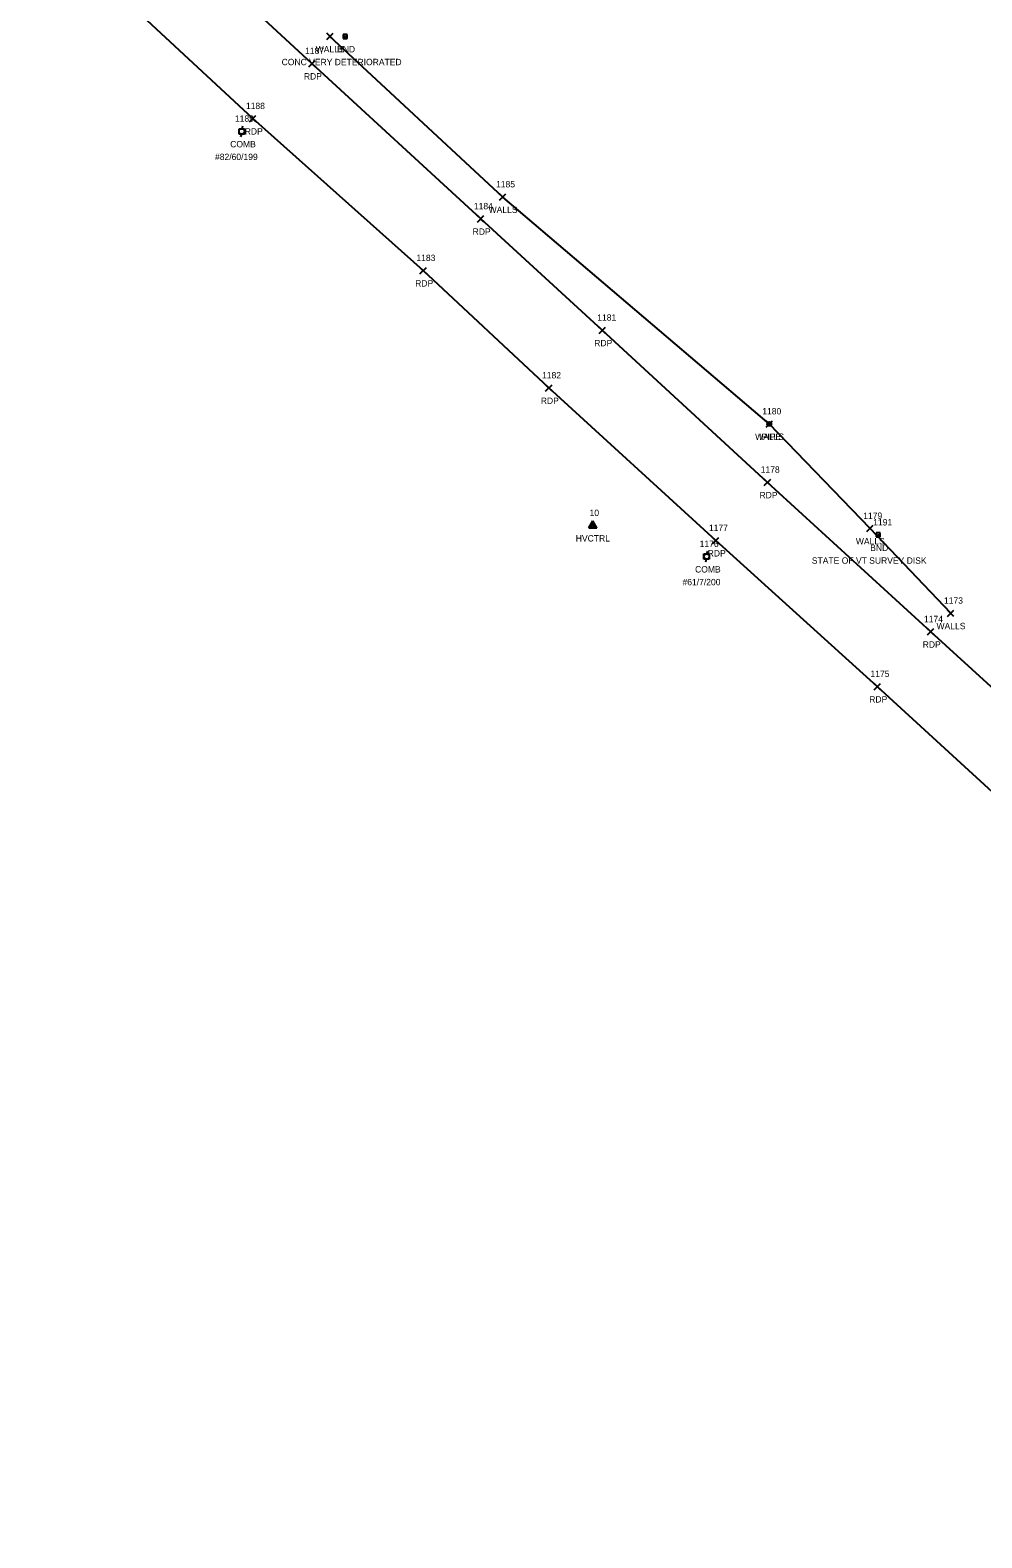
# Model space of a CAD drawing. Extents: x 1519347 to 1522636, y 378779 to 379832.
# Drawn here: x 1521076 to 1521374.1, y 378831 to 379303.7 of the extents above; entities that cross this region are included whole.
import ezdxf

# ---------------------------------------------------------------- set-up
doc = ezdxf.new("R2010")
doc.units = 0
for name, color, linetype in [('C_A', 7, 'Continuous'), ('C_I', 7, 'Continuous'), ('CPSM', 7, 'Continuous'), ('L_A', 7, 'Continuous'), ('L_I', 7, 'Continuous'), ('L_TIC', 7, 'Continuous'), ('LWS', 7, 'Continuous'), ('M_A', 7, 'Continuous'), ('M_C', 7, 'Continuous'), ('M_I', 7, 'Continuous'), ('MHBP', 7, 'Continuous'), ('MPIP', 7, 'Continuous'), ('P_A', 7, 'Continuous'), ('P_I', 7, 'Continuous'), ('P_TIC', 7, 'Continuous'), ('PET', 7, 'Continuous'), ('U_A', 7, 'Continuous'), ('U_C', 7, 'Continuous'), ('U_I', 7, 'Continuous'), ('UP', 7, 'Continuous')]:
    doc.layers.add(name, color=color, linetype=linetype)

msp = doc.modelspace()

# ---------------------------------------------------------------- linework, layer by layer
at = {"layer": 'CPSM'}
for p, q in [((1521250.98, 379147.68), (1521252.23, 379149.84)), ((1521250.98, 379147.68), (1521252.23, 379148.4)), ((1521253.48, 379147.68), (1521252.23, 379149.84)), ((1521252.23, 379148.4), (1521252.23, 379149.84)), ((1521252.23, 379148.4), (1521252.23, 379148.4)), ((1521252.23, 379148.4), (1521253.48, 379147.68)), ((1521250.98, 379147.68), (1521253.48, 379147.68))]:
    msp.add_line(p, q, dxfattribs=at)
at = {"layer": 'L_TIC'}
for points in [[(1521168.88, 379300.74), (1521170.88, 379302.74)], [(1521170.88, 379300.74), (1521168.88, 379302.74)], [(1521223.05, 379250.41), (1521225.05, 379252.41)], [(1521225.05, 379250.41), (1521223.05, 379252.41)], [(1521306.56, 379179.25), (1521308.56, 379181.25)], [(1521308.56, 379179.25), (1521306.56, 379181.25)], [(1521338.12, 379146.49), (1521340.12, 379148.49)], [(1521340.12, 379146.49), (1521338.12, 379148.49)], [(1521363.4, 379119.9), (1521365.4, 379121.9)], [(1521365.4, 379119.9), (1521363.4, 379121.9)]]:
    msp.add_lwpolyline(points, dxfattribs=at)
at = {"layer": 'LWS'}
msp.add_lwpolyline([(1521364.4, 379120.9), (1521339.12, 379147.49), (1521307.56, 379180.25), (1521224.05, 379251.41), (1521169.88, 379301.74)], dxfattribs=at)
at = {"layer": 'MHBP'}
for p, q in [((1521175.28, 379302.38), (1521174.03, 379302.38)), ((1521174.03, 379302.38), (1521174.03, 379301.13)), ((1521175.28, 379302.38), (1521174.03, 379302.38)), ((1521174.03, 379302.38), (1521174.03, 379301.13)), ((1521174.03, 379301.13), (1521175.28, 379301.13)), ((1521174.03, 379301.13), (1521175.28, 379301.13)), ((1521175.28, 379301.13), (1521175.28, 379302.38)), ((1521175.28, 379301.13), (1521175.28, 379302.38)), ((1521342.33, 379146.09), (1521341.08, 379146.09)), ((1521341.08, 379146.09), (1521341.08, 379144.84)), ((1521342.33, 379146.09), (1521341.08, 379146.09)), ((1521341.08, 379146.09), (1521341.08, 379144.84)), ((1521341.08, 379144.84), (1521342.33, 379144.84)), ((1521341.08, 379144.84), (1521342.33, 379144.84)), ((1521342.33, 379144.84), (1521342.33, 379146.09)), ((1521342.33, 379144.84), (1521342.33, 379146.09))]:
    msp.add_line(p, q, dxfattribs=at)
for centre in [(1521174.63, 379301.72), (1521341.68, 379145.42)]:
    msp.add_circle(centre, 0.0833, dxfattribs=at)
at = {"layer": 'MPIP'}
for radius in [0.625, 0.0833]:
    msp.add_circle((1521307.56, 379180.25), radius, dxfattribs=at)
at = {"layer": 'P_TIC'}
for points in [[(1521163.23, 379292.24), (1521165.23, 379294.24)], [(1521165.23, 379292.24), (1521163.23, 379294.24)], [(1521144.7, 379274.98), (1521146.7, 379276.98)], [(1521146.7, 379274.98), (1521144.7, 379276.98)], [(1521216.12, 379243.56), (1521218.12, 379245.56)], [(1521218.12, 379243.56), (1521216.12, 379245.56)], [(1521198.1, 379227.33), (1521200.1, 379229.33)], [(1521200.1, 379227.33), (1521198.1, 379229.33)], [(1521254.2, 379208.61), (1521256.2, 379210.61)], [(1521256.2, 379208.61), (1521254.2, 379210.61)], [(1521237.48, 379190.54), (1521239.48, 379192.54)], [(1521239.48, 379190.54), (1521237.48, 379192.54)], [(1521305.99, 379160.95), (1521307.99, 379162.95)], [(1521307.99, 379160.95), (1521305.99, 379162.95)], [(1521289.76, 379142.7), (1521291.76, 379144.7)], [(1521291.76, 379142.7), (1521289.76, 379144.7)], [(1521357.14, 379114.1), (1521359.14, 379116.1)], [(1521359.14, 379114.1), (1521357.14, 379116.1)], [(1521340.37, 379096.91), (1521342.37, 379098.91)], [(1521342.37, 379096.91), (1521340.37, 379098.91)]]:
    msp.add_lwpolyline(points, dxfattribs=at)
at = {"layer": 'PET'}
for points in [[(1521585.34, 378845.78), (1521563.15, 378884.68), (1521538.32, 378926.95), (1521509.26, 378967.74), (1521474.33, 379006.93), (1521436.59, 379043.66), (1521409.99, 379067.83), (1521358.14, 379115.1), (1521306.99, 379161.95), (1521255.2, 379209.61), (1521217.12, 379244.56), (1521164.23, 379293.24), (1521067.69, 379382.51), (1520997.97, 379446.49), (1520922.59, 379515.2), (1520874.63, 379556.58), (1520808.13, 379606.22), (1520782.76, 379623.68), (1520756.28, 379641.62), (1520757.14, 379649.49)], [(1521566.64, 378831.03), (1521543.56, 378872.83), (1521519.09, 378912.94), (1521489.55, 378952.75), (1521455.86, 378990.48), (1521419.87, 379025.89), (1521341.37, 379097.91), (1521290.76, 379143.7), (1521238.48, 379191.54), (1521199.1, 379228.33), (1521145.7, 379275.98), (1521050.75, 379364.16), (1520980.24, 379428.62), (1520906.12, 379495.86), (1520857.57, 379538.26), (1520794, 379586.56), (1520766.68, 379604.35), (1520729.49, 379628.42), (1520699.13, 379644.75)]]:
    msp.add_lwpolyline(points, dxfattribs=at)
at = {"layer": 'UP'}
for p, q in [((1521141.42, 379271.16), (1521141.42, 379272.82)), ((1521141.42, 379272.82), (1521143.09, 379272.82)), ((1521142.5, 379273.66), (1521142.25, 379272.82)), ((1521142.25, 379271.99), (1521142.25, 379271.99)), ((1521143.09, 379272.82), (1521143.09, 379271.16)), ((1521143.09, 379271.16), (1521141.42, 379271.16)), ((1521142, 379270.32), (1521142.25, 379271.16)), ((1521287.07, 379137.84), (1521287.07, 379139.51)), ((1521287.07, 379139.51), (1521288.74, 379139.51)), ((1521288.16, 379140.34), (1521287.91, 379139.51)), ((1521288.74, 379139.51), (1521288.74, 379137.84)), ((1521288.74, 379137.84), (1521287.07, 379137.84)), ((1521287.66, 379137.01), (1521287.91, 379137.84)), ((1521287.91, 379138.68), (1521287.91, 379138.68))]:
    msp.add_line(p, q, dxfattribs=at)
for centre in [(1521142.25, 379271.99), (1521287.91, 379138.68)]:
    msp.add_circle(centre, 0.833, dxfattribs=at)

# ---------------------------------------------------------------- texts
at = {"layer": 'C_A'}
msp.add_text('HVCTRL', height=2, dxfattribs=at).set_placement((1521246.92, 379143.4))
at = {"layer": 'C_I'}
msp.add_text('10', height=2, dxfattribs=at).set_placement((1521251.24, 379151.4))
at = {"layer": 'L_A'}
for p in [(1521165.42, 379296.74), (1521219.6, 379246.41), (1521303.11, 379175.25), (1521334.67, 379142.49), (1521359.95, 379115.9)]:
    msp.add_text('WALLS', height=2, dxfattribs=at).set_placement(p)
at = {"layer": 'L_I'}
for s, p in [('1185', (1521221.93, 379254.41)), ('1180', (1521305.35, 379183.25)), ('1179', (1521336.99, 379150.49)), ('1173', (1521362.28, 379123.9))]:
    msp.add_text(s, height=2, dxfattribs=at).set_placement(p)
at = {"layer": 'M_A'}
for s, p in [('BND', (1521172.12, 379296.73)), ('IPIPE', (1521304.4, 379175.25)), ('BND', (1521339.17, 379140.43))]:
    msp.add_text(s, height=2, dxfattribs=at).set_placement(p)
at = {"layer": 'M_C'}
for s, p in [('CONC VERY DETERIORATED', (1521154.75, 379292.73)), ('STATE OF VT SURVEY DISK', (1521320.88, 379136.43))]:
    msp.add_text(s, height=2, dxfattribs=at).set_placement(p)
at = {"layer": 'M_I'}
for s, p in [('1180', (1521305.35, 379183.25)), ('1191', (1521340.12, 379148.43))]:
    msp.add_text(s, height=2, dxfattribs=at).set_placement(p)
at = {"layer": 'P_A'}
for p in [(1521161.72, 379288.24), (1521143.19, 379270.98), (1521214.61, 379239.56), (1521196.59, 379223.33), (1521252.69, 379204.61), (1521235.96, 379186.54), (1521304.48, 379156.95), (1521288.25, 379138.7), (1521355.62, 379110.1), (1521338.86, 379092.91)]:
    msp.add_text('RDP', height=2, dxfattribs=at).set_placement(p)
at = {"layer": 'P_I'}
for s, p in [('1187', (1521162.1, 379296.24)), ('1188', (1521143.57, 379278.98)), ('1184', (1521215, 379247.56)), ('1183', (1521196.98, 379231.33)), ('1181', (1521253.65, 379212.61)), ('1182', (1521236.35, 379194.54)), ('1178', (1521304.86, 379164.95)), ('1177', (1521288.64, 379146.7)), ('1174', (1521356.01, 379118.1)), ('1175', (1521339.25, 379100.91))]:
    msp.add_text(s, height=2, dxfattribs=at).set_placement(p)
at = {"layer": 'U_A'}
for p in [(1521138.64, 379266.99), (1521284.29, 379133.68)]:
    msp.add_text('COMB', height=2, dxfattribs=at).set_placement(p)
at = {"layer": 'U_C'}
for s, p in [('#82/60/199', (1521133.88, 379262.99)), ('#61/7/200', (1521280.36, 379129.68))]:
    msp.add_text(s, height=2, dxfattribs=at).set_placement(p)
at = {"layer": 'U_I'}
for s, p in [('1189', (1521140.12, 379274.99)), ('1176', (1521285.73, 379141.68))]:
    msp.add_text(s, height=2, dxfattribs=at).set_placement(p)

doc.saveas('drawing.dxf')
